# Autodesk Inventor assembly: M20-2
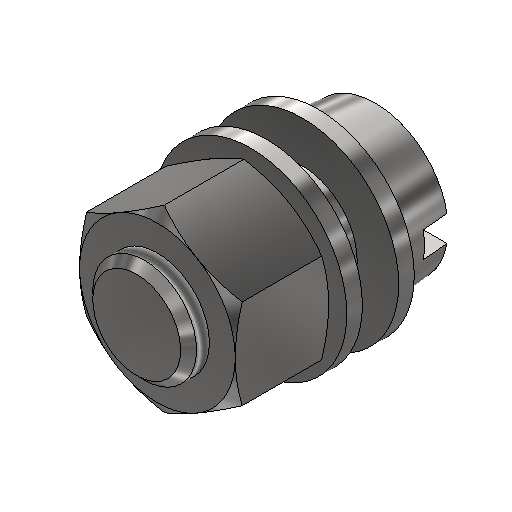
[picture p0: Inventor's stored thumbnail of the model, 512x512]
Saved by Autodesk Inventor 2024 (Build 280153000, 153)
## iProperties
Company: ATC
ClientObjectVersion: 1
Created: 2023-03
Part Number: M20-2
Document SubType Name: Assembly
Designer: Andrzej Jaskulski
Checked By: A.J.
Engr Approved By: Andrzej Jaskulski
Mfg Approved By: Andrzej Jaskulski
Authority: A.J.
Author: Andrzej Jaskulski
Title: A.J.: Kurs R2024-MEP
Revision Number: 1/24
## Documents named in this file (4)
- C:\Users\AndJas\Documents\R2024-MEP\Obszar roboczy\SPEC\GOTOWE\SPEC-GOTOWE\Design Accelerator\M20-2.iam
- C:\Users\AndJas\Documents\R2024-MEP\Obszar roboczy\SPEC\GOTOWE\SPEC-GOTOWE\PN\PN-78_M-82005 - 21.ipt
- C:\Users\AndJas\Documents\R2024-MEP\Obszar roboczy\SPEC\GOTOWE\SPEC-GOTOWE\PN\PN-85_M-82215 - M 20 x 35 - 2,5.ipt
- C:\Users\AndJas\Documents\R2024-MEP\Obszar roboczy\SPEC\GOTOWE\SPEC-GOTOWE\PN\PN-86_M-82144 - M20.ipt
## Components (4 placed, 3 different names)
1. PN-78/M-82005 21:1
2. PN-85/M-82215 M 20 x 35:1
3. PN-78/M-82005 21:2
4. PN-86/M-82144 M20:1
